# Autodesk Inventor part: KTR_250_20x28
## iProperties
Shininess: 64.0
Length Units: 11269
Angle Units: 11279
Time Units: 11290
Mass Units: 11283
Length Display Precision: 3
Angle Display Precision: 2
Compacted: True
Part Number: KTR_250_20x28
Document SubType Name: Modeling
Created: 2003-05
Material: Stahl (schweißbar)
Designer: kb5
Cost Center: 0,3 kg
Authority: 40094,49 mm^3
Density: 7.86 g/cm^3
Density: 0.0
Volumn: 0.0
Area: 0.0
PropertySet Name: Model Information
Control State: 0
Master: False
Checked Out: False
SaveDate: 2004-08-05
SaveTime: 12:44
TotalMass: 0,3 kg
TotalVolume: 40094,49 mm^3
Author: kb5
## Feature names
1. Basis1
